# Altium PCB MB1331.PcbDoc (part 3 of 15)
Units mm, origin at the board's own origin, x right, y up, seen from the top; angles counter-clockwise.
Board outline 169.25 x 173.25 mm, 6 copper layers (Top Layer, Signal Layer 1, Signal Layer 2, Signal Layer 3, Signal Layer 4, Bottom Layer), stack 1.556 mm thick; 871 components, 699 nets, 3244 pads, 2370 vias.
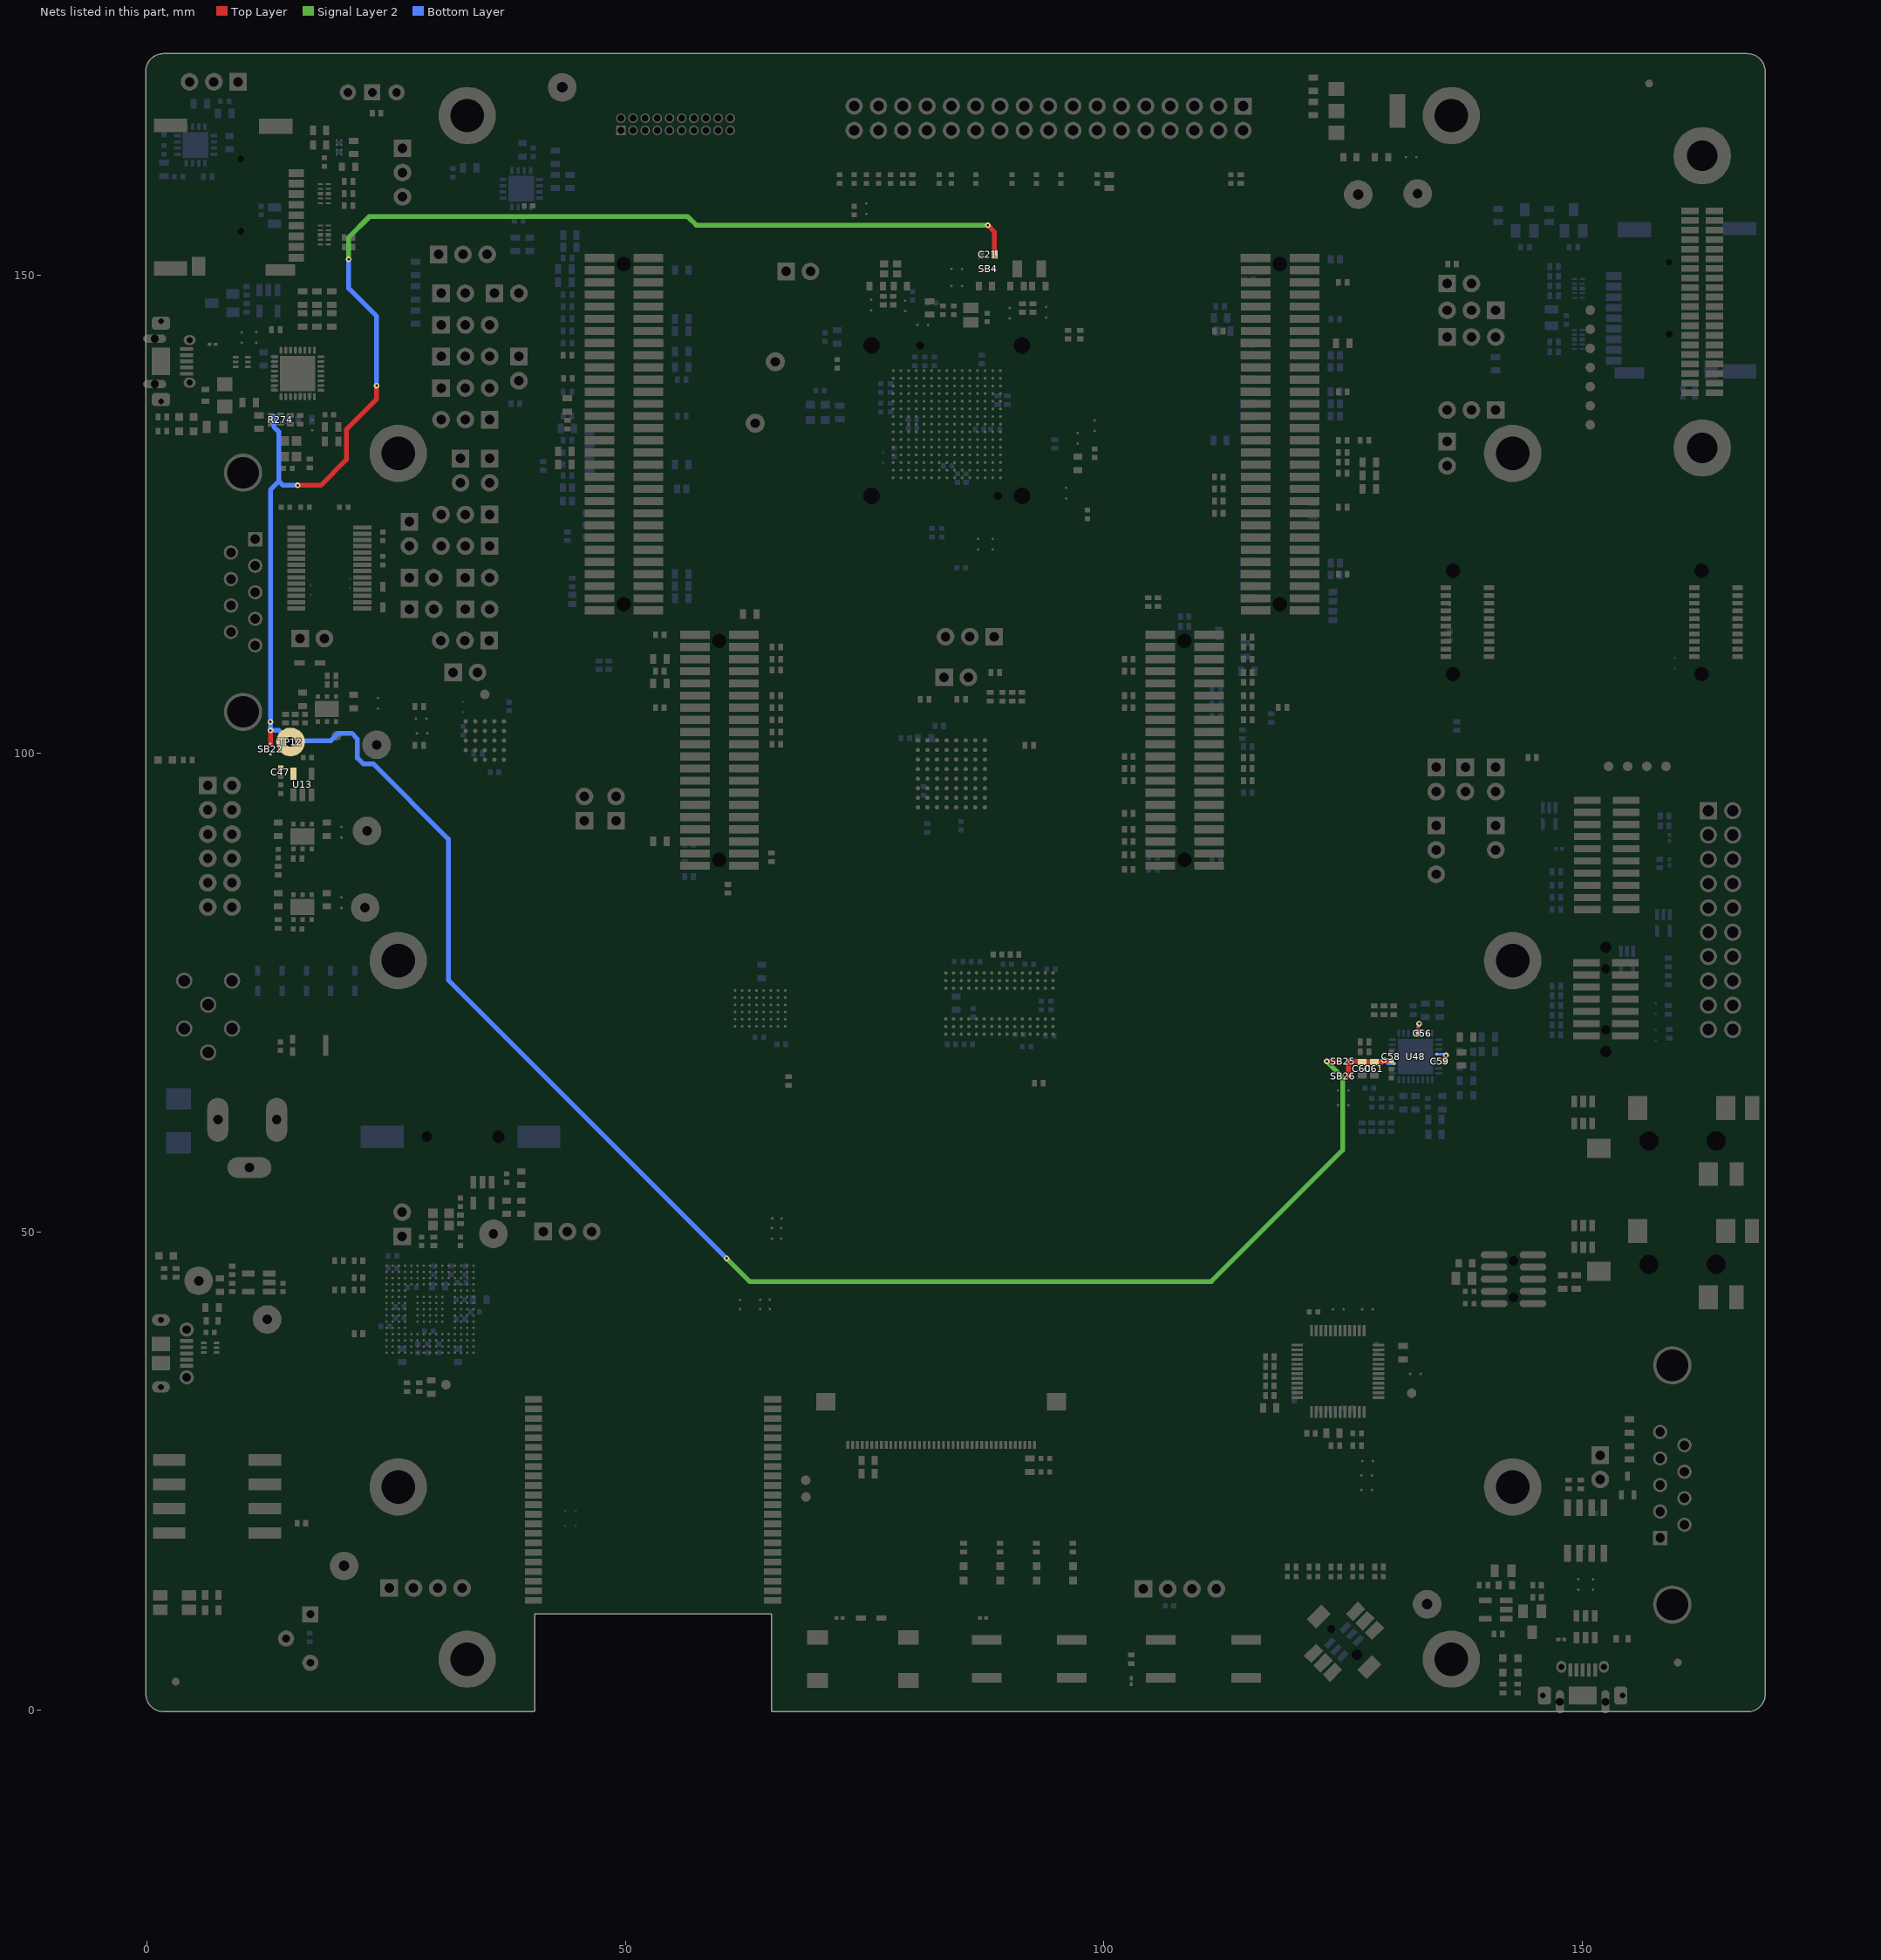
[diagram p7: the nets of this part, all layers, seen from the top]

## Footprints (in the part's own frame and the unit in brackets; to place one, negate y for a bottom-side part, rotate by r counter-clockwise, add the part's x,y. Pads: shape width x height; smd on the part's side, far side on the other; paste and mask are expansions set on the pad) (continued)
ICC_TFBGA225_13X13_STM32H7B3NIH6Q_P080__SOCKET_IRONWOOD_CS1222291MF_REV-A_WITHOUT-3D-SOCKET [mm] "MCD-01577"
  round 0.3 smd mask+0.05: A1(-5.6,5.6) A2(-4.8,5.6) A3(-4,5.6) A4(-3.2,5.6) A5(-2.4,5.6) A6(-1.6,5.6) A7(-0.8,5.6) A8(0,5.6) A9(0.8,5.6) A10(1.6,5.6) A11(2.4,5.6) A12(3.2,5.6) A13(4,5.6) A14(4.8,5.6) A15(5.6,5.6) B1(-5.6,4.8) B2(-4.8,4.8) B3(-4,4.8) B4(-3.2,4.8) B5(-2.4,4.8) B6(-1.6,4.8) B7(-0.8,4.8) B8(0,4.8) B9(0.8,4.8) B10(1.6,4.8) B11(2.4,4.8) B12(3.2,4.8) B13(4,4.8) B14(4.8,4.8) B15(5.6,4.8) C1(-5.6,4) C2(-4.8,4) C3(-4,4) C4(-3.2,4) C5(-2.4,4) C6(-1.6,4) C7(-0.8,4) C8(0,4) C9(0.8,4) C10(1.6,4) C11(2.4,4) C12(3.2,4) C13(4,4) C14(4.8,4) C15(5.6,4) D1(-5.6,3.2) D2(-4.8,3.2) D3(-4,3.2) D4(-3.2,3.2) D5(-2.4,3.2) D6(-1.6,3.2) D7(-0.8,3.2) D8(0,3.2) D9(0.8,3.2) D10(1.6,3.2) D11(2.4,3.2) D12(3.2,3.2) D13(4,3.2) D14(4.8,3.2) D15(5.6,3.2) E1(-5.6,2.4) E2(-4.8,2.4) E3(-4,2.4) E4(-3.2,2.4) E5(-2.4,2.4) E6(-1.6,2.4) E7(-0.8,2.4) E8(0,2.4) E9(0.8,2.4) E10(1.6,2.4) E11(2.4,2.4) E12(3.2,2.4) E13(4,2.4) E14(4.8,2.4) E15(5.6,2.4) F1(-5.6,1.6) F2(-4.8,1.6) F3(-4,1.6) F4(-3.2,1.6) F5(-2.4,1.6) F6(-1.6,1.6) F7(-0.8,1.6) F8(0,1.6) F9(0.8,1.6) F10(1.6,1.6) F11(2.4,1.6) F12(3.2,1.6) F13(4,1.6) F14(4.8,1.6) F15(5.6,1.6) G1(-5.6,0.8) G2(-4.8,0.8) G3(-4,0.8) G4(-3.2,0.8) G5(-2.4,0.8) G6(-1.6,0.8) G7(-0.8,0.8) G8(0,0.8) G9(0.8,0.8) G10(1.6,0.8) G11(2.4,0.8) G12(3.2,0.8) G13(4,0.8) G14(4.8,0.8) G15(5.6,0.8) H1(-5.6,0) H2(-4.8,0) H3(-4,0) H4(-3.2,0) H5(-2.4,0) H6(-1.6,0) H7(-0.8,0) H8(0,0) H9(0.8,0) H10(1.6,0) H11(2.4,0) H12(3.2,0) H13(4,0) H14(4.8,0) H15(5.6,0) J1(-5.6,-0.8) J2(-4.8,-0.8) J3(-4,-0.8) J4(-3.2,-0.8) J5(-2.4,-0.8) J6(-1.6,-0.8) J7(-0.8,-0.8) J8(0,-0.8) J9(0.8,-0.8) J10(1.6,-0.8) J11(2.4,-0.8) J12(3.2,-0.8) J13(4,-0.8) J14(4.8,-0.8) J15(5.6,-0.8) K1(-5.6,-1.6) K2(-4.8,-1.6) K3(-4,-1.6) K4(-3.2,-1.6) K5(-2.4,-1.6) K6(-1.6,-1.6) K7(-0.8,-1.6) K8(0,-1.6) K9(0.8,-1.6) K10(1.6,-1.6) K11(2.4,-1.6) K12(3.2,-1.6) K13(4,-1.6) K14(4.8,-1.6) K15(5.6,-1.6) L1(-5.6,-2.4) L2(-4.8,-2.4) L3(-4,-2.4) L4(-3.2,-2.4) L5(-2.4,-2.4) L6(-1.6,-2.4) L7(-0.8,-2.4) L8(0,-2.4) L9(0.8,-2.4) L10(1.6,-2.4) L11(2.4,-2.4) L12(3.2,-2.4) L13(4,-2.4) L14(4.8,-2.4) L15(5.6,-2.4) M1(-5.6,-3.2) M2(-4.8,-3.2) M3(-4,-3.2) M4(-3.2,-3.2) M5(-2.4,-3.2) M6(-1.6,-3.2) M7(-0.8,-3.2) M8(0,-3.2) M9(0.8,-3.2) M10(1.6,-3.2) M11(2.4,-3.2) M12(3.2,-3.2) M13(4,-3.2) M14(4.8,-3.2) M15(5.6,-3.2) N1(-5.6,-4) N2(-4.8,-4) N3(-4,-4) N4(-3.2,-4) N5(-2.4,-4) N6(-1.6,-4) N7(-0.8,-4) N8(0,-4) N9(0.8,-4) N10(1.6,-4) N11(2.4,-4) N12(3.2,-4) N13(4,-4) N14(4.8,-4) N15(5.6,-4) P1(-5.6,-4.8) P2(-4.8,-4.8) P3(-4,-4.8) P4(-3.2,-4.8) P5(-2.4,-4.8) P6(-1.6,-4.8) P7(-0.8,-4.8) P8(0,-4.8) P9(0.8,-4.8) P10(1.6,-4.8) P11(2.4,-4.8) P12(3.2,-4.8) P13(4,-4.8) P14(4.8,-4.8) P15(5.6,-4.8) R1(-5.6,-5.6) R2(-4.8,-5.6) R3(-4,-5.6) R4(-3.2,-5.6) R5(-2.4,-5.6) R6(-1.6,-5.6) R7(-0.8,-5.6) R8(0,-5.6) R9(0.8,-5.6) R10(1.6,-5.6) R11(2.4,-5.6) R12(3.2,-5.6) R13(4,-5.6) R14(4.8,-5.6) R15(5.6,-5.6)
  round 0 hole 0.85 unplated mask+0.05: NPTH1(7.487,5.322) NPTH2(-8.238,-2.783)
  round 0 hole 1.71 unplated mask+0.05: PTH1(-8.238,7.862) PTH2(7.487,7.862) PTH3(7.487,-7.863) PTH4(-8.238,-7.863)
  Bottom Layer keep-out circle w0.01: c7.487,7.862 r2.5
  Bottom Layer keep-out circle w0.01: c-8.238,7.862 r2.5
  Bottom Layer keep-out circle w0.01: c-8.238,-7.863 r2.5
  Bottom Layer keep-out circle w0.01: c7.487,-7.863 r2.5
  Bottom Layer keep-out region: -0.376,0 -0.376,-2.5 1.224,-2.5 5.024,-6.3 5.076,-6.378 5.094,-6.469 5.094,-6.469 5.094,-6.63 5.028,-6.963 4.839,-7.245 4.557,-7.434 4.224,-7.5 4.224,-7.5 -0.376,-7.5 -0.376,-10.365 9.988,-10.365 9.988,10.365 -0.376,10.365 -0.376,7.5 4.224,7.5 4.557,7.434 4.839,7.245 5.028,6.963 5.094,6.63 5.094,6.63 5.094,6.469 5.076,6.378 5.024,6.3 5.024,6.3 1.224,2.5 -0.376,2.5 -0.376,0 2.124,0 2.124,1.6 5.924,5.4 6.002,5.452 6.093,5.47 6.093,5.47 6.254,5.47 6.587,5.404 6.869,5.215 7.058,4.933 7.124,4.6 7.124,4.6 7.124,-4.6 7.058,-4.933 6.869,-5.215 6.587,-5.404 6.254,-5.47 6.254,-5.47 6.093,-5.47 6.002,-5.452 5.924,-5.4 5.924,-5.4 2.124,-1.6 2.124,0
  Bottom Layer keep-out region: -0.376,0 -0.376,2.5 -1.976,2.5 -5.776,6.3 -5.828,6.378 -5.846,6.469 -5.846,6.469 -5.846,6.63 -5.78,6.963 -5.591,7.245 -5.309,7.434 -4.976,7.5 -4.976,7.5 -0.376,7.5 -0.376,10.365 -10.74,10.365 -10.74,-10.365 -0.376,-10.365 -0.376,-7.5 -4.976,-7.5 -5.309,-7.434 -5.591,-7.245 -5.78,-6.963 -5.846,-6.63 -5.846,-6.63 -5.846,-6.469 -5.828,-6.378 -5.776,-6.3 -5.776,-6.3 -1.976,-2.5 -0.376,-2.5 -0.376,0 -2.876,0 -2.876,-1.6 -6.676,-5.4 -6.754,-5.452 -6.845,-5.47 -6.845,-5.47 -7.006,-5.47 -7.339,-5.404 -7.621,-5.215 -7.81,-4.933 -7.876,-4.6 -7.876,-4.6 -7.876,4.6 -7.81,4.933 -7.621,5.215 -7.339,5.404 -7.006,5.47 -7.006,5.47 -6.845,5.47 -6.754,5.452 -6.676,5.4 -6.676,5.4 -2.876,1.6 -2.876,0
  silkscreen extent -9.65,-9.13 8.75,9.28, body extent -6.55,-6.55 6.55,6.55, height 1.21
ICC_UFBGA201_176+25_10X10_P065 [mm] "IPC"
  round 0.25 smd mask+0.05: A1(-4.55,4.55) A2(-3.9,4.55) A3(-3.25,4.55) A4(-2.6,4.55) A5(-1.95,4.55) A6(-1.3,4.55) A7(-0.65,4.55) A8(0,4.55) A9(0.65,4.55) A10(1.3,4.55) A11(1.95,4.55) A12(2.6,4.55) A13(3.25,4.55) A14(3.9,4.55) A15(4.55,4.55) B1(-4.55,3.9) B2(-3.9,3.9) B3(-3.25,3.9) B4(-2.6,3.9) B5(-1.95,3.9) B6(-1.3,3.9) B7(-0.65,3.9) B8(0,3.9) B9(0.65,3.9) B10(1.3,3.9) B11(1.95,3.9) B12(2.6,3.9) B13(3.25,3.9) B14(3.9,3.9) B15(4.55,3.9) C1(-4.55,3.25) C2(-3.9,3.25) C3(-3.25,3.25) C4(-2.6,3.25) C5(-1.95,3.25) C6(-1.3,3.25) C7(-0.65,3.25) C8(0,3.25) C9(0.65,3.25) C10(1.3,3.25) C11(1.95,3.25) C12(2.6,3.25) C13(3.25,3.25) C14(3.9,3.25) C15(4.55,3.25) D1(-4.55,2.6) D2(-3.9,2.6) D3(-3.25,2.6) D4(-2.6,2.6) D5(-1.95,2.6) D6(-1.3,2.6) D7(-0.65,2.6) D8(0,2.6) D9(0.65,2.6) D10(1.3,2.6) D11(1.95,2.6) D12(2.6,2.6) D13(3.25,2.6) D14(3.9,2.6) D15(4.55,2.6) E1(-4.55,1.95) E2(-3.9,1.95) E3(-3.25,1.95) E4(-2.6,1.95) E12(2.6,1.95) E13(3.25,1.95) E14(3.9,1.95) E15(4.55,1.95) F1(-4.55,1.3) F2(-3.9,1.3) F3(-3.25,1.3) F4(-2.6,1.3) F6(-1.3,1.3) F7(-0.65,1.3) F8(0,1.3) F9(0.65,1.3) F10(1.3,1.3) F12(2.6,1.3) F13(3.25,1.3) F14(3.9,1.3) F15(4.55,1.3) G1(-4.55,0.65) G2(-3.9,0.65) G3(-3.25,0.65) G4(-2.6,0.65) G6(-1.3,0.65) G7(-0.65,0.65) G8(0,0.65) G9(0.65,0.65) G10(1.3,0.65) G12(2.6,0.65) G13(3.25,0.65) G14(3.9,0.65) G15(4.55,0.65) H1(-4.55,0) H2(-3.9,0) H3(-3.25,0) H4(-2.6,0) H6(-1.3,0) H7(-0.65,0) H8(0,0) H9(0.65,0) H10(1.3,0) H12(2.6,0) H13(3.25,0) H14(3.9,0) H15(4.55,0) J1(-4.55,-0.65) J2(-3.9,-0.65) J3(-3.25,-0.65) J4(-2.6,-0.65) J6(-1.3,-0.65) J7(-0.65,-0.65) J8(0,-0.65) J9(0.65,-0.65) J10(1.3,-0.65) J12(2.6,-0.65) J13(3.25,-0.65) J14(3.9,-0.65) J15(4.55,-0.65) K1(-4.55,-1.3) K2(-3.9,-1.3) K3(-3.25,-1.3) K4(-2.6,-1.3) K6(-1.3,-1.3) K7(-0.65,-1.3) K8(0,-1.3) K9(0.65,-1.3) K10(1.3,-1.3) K12(2.6,-1.3) K13(3.25,-1.3) K14(3.9,-1.3) K15(4.55,-1.3) L1(-4.55,-1.95) L2(-3.9,-1.95) L3(-3.25,-1.95) L4(-2.6,-1.95) L12(2.6,-1.95) L13(3.25,-1.95) L14(3.9,-1.95) L15(4.55,-1.95) M1(-4.55,-2.6) M2(-3.9,-2.6) M3(-3.25,-2.6) M4(-2.6,-2.6) M5(-1.95,-2.6) M6(-1.3,-2.6) M7(-0.65,-2.6) M8(0,-2.6) M9(0.65,-2.6) M10(1.3,-2.6) M11(1.95,-2.6) M12(2.6,-2.6) M13(3.25,-2.6) M14(3.9,-2.6) M15(4.55,-2.6) N1(-4.55,-3.25) N2(-3.9,-3.25) N3(-3.25,-3.25) N4(-2.6,-3.25) N5(-1.95,-3.25) N6(-1.3,-3.25) N7(-0.65,-3.25) N8(0,-3.25) N9(0.65,-3.25) N10(1.3,-3.25) N11(1.95,-3.25) N12(2.6,-3.25) N13(3.25,-3.25) N14(3.9,-3.25) N15(4.55,-3.25) P1(-4.55,-3.9) P2(-3.9,-3.9) P3(-3.25,-3.9) P4(-2.6,-3.9) P5(-1.95,-3.9) P6(-1.3,-3.9) P7(-0.65,-3.9) P8(0,-3.9) P9(0.65,-3.9) P10(1.3,-3.9) P11(1.95,-3.9) P12(2.6,-3.9) P13(3.25,-3.9) P14(3.9,-3.9) P15(4.55,-3.9) R1(-4.55,-4.55) R2(-3.9,-4.55) R3(-3.25,-4.55) R4(-2.6,-4.55) R5(-1.95,-4.55) R6(-1.3,-4.55) R7(-0.65,-4.55) R8(0,-4.55) R9(0.65,-4.55) R10(1.3,-4.55) R11(1.95,-4.55) R12(2.6,-4.55) R13(3.25,-4.55) R14(3.9,-4.55) R15(4.55,-4.55)
  silkscreen extent -5.22,-5.07 5.07,5.23, body extent -5.07,-5.07 5.07,5.07, height 0.61
IND_0402_MURATA_BLM15H_H0P5 [mm] "MCD-01610"
  rect 0.65x0.9 smd mask+0.05: 1(-0.475,0) 2(0.475,0)
  silkscreen extent -0.05,-0.28 0.05,0.28, body extent -0.53,-0.28 0.53,0.28, height 0.55
IND_0603_H0P8 [mm]
  rect 0.7x0.9 smd mask+0.05: 1(-0.7,0) 2(0.7,0)
  silkscreen extent -0.2,-0.4 0.2,0.4, body extent -0.8,-0.4 0.8,0.4, height 0.8
L0603 [mm]
  rect 0.8x0.95 smd mask+0.05: 1(-0.8,0) 2(0.8,0)
  silkscreen extent -1.33,-0.6 1.33,0.6, body extent -0.87,-0.47 0.87,0.47, height 0.95
L0805_H0P9 [mm]
  rect 1.1x1.6 smd mask+0.05: 1(-0.75,0) 2(0.75,0)
  silkscreen extent -0.08,-0.7 0.08,0.7, body extent -1.07,-0.7 1.07,0.7, height 1.2
LED_0603_OSRAM_LG-Q396-PS-35_GREEN_1A2K_H0P4 [mm]
  rect 0.8x0.8 smd mask+0.05: 1(-0.75,0) 2(0.75,0)
  silkscreen extent -0.85,-0.53 1.28,0.53, body extent -0.85,-0.45 0.85,0.45, height 0.6
LED_0603_OSRAM_LO-Q976-PS-25_ORANGE_1A2K_H0P8 [mm]
  rect 0.8x0.8 smd mask+0.05: 1(-0.75,0) 2(0.75,0)
  silkscreen extent -0.85,-0.53 1.28,0.53, body extent -0.85,-0.45 0.85,0.45, height 0.8
LED_0603_OSRAM_LY-Q396-P1Q2-36_YELLOW_1A2K_H0P4 [mm]
  rect 0.8x0.8 smd mask+0.05: 1(-0.75,0) 2(0.75,0)
  silkscreen extent -0.85,-0.53 1.28,0.53, body extent -0.85,-0.45 0.85,0.45, height 0.4
LED_0603_VISHAY_VLMS1300-GS08_RED_1A2K_H0P8 [mm]
  rect 0.8x0.8 smd mask+0.05: 1(-0.75,0) 2(0.75,0)
  silkscreen extent -0.85,-0.53 1.28,0.53, body extent -0.85,-0.45 0.85,0.45, height 0.8
LED_BI-GR_HSMF-A201-A00J1 [mm] "MCD-00051"
  rect 1.1x1.5 smd mask+0.05: 1(-0.75,-1.5) 2(-0.75,1.5) 3(0.75,1.5) 4(0.75,-1.5)
  silkscreen extent -1.65,-1.85 1.5,1.7, body extent -1.5,-1.85 1.5,1.85, height 2.1
MIRE_PLACE_SMD_0P8MM [mm]
  round 0.8 smd paste-10 mask+0.2: 1(0,0)
  Top Layer keep-out circle w0.01: c0,0 r0.804
MOD_WIFI_INVENTEK_ISM43362 [mm]
  rect 1.8x0.7 smd mask+0.1: 1(12.5,-12.3) 2(12.5,-11.3) 3(12.5,-10.3) 4(12.5,-9.3) 5(12.5,-8.3) 6(12.5,-7.3) 7(12.5,-6.3) 8(12.5,-5.3) 9(12.5,-4.3) 10(12.5,-3.3) 11(12.5,-2.3) 12(12.5,-1.3) 13(12.5,-0.3) 14(12.5,0.7) 15(12.5,1.7) 16(12.5,2.7) 17(12.5,3.7) 18(12.5,4.7) 19(12.5,5.7) 20(12.5,6.7) 21(12.5,7.7) 22(12.5,8.7) 23(-12.5,8.7) 24(-12.5,7.7) 25(-12.5,6.7) 26(-12.5,5.7) 27(-12.5,4.7) 28(-12.5,3.7) 29(-12.5,2.7) 30(-12.5,1.7) 31(-12.5,0.7) 32(-12.5,-0.3) 33(-12.5,-1.3) 34(-12.5,-2.3) 35(-12.5,-3.3) 36(-12.5,-4.3) 37(-12.5,-5.3) 38(-12.5,-6.3) 39(-12.5,-7.3) 40(-12.5,-8.3) 41(-12.5,-9.3) 42(-12.5,-10.3) 43(-12.5,-11.3) 44(-12.5,-12.3)
  Keep-Out Layer region: -12.5,20 12.5,20 12.5,10 -12.5,10
  silkscreen extent -12.7,-20.2 13.4,20.2, body extent -12.5,-20 12.5,20.19, height 4.1
MOS_SOT23 [mm]
  rect 1x1.4 smd mask+0.05: 1(-0.95,-1.1) 2(0.95,-1.1) 3(0,1.1)
  silkscreen extent -1.63,-0.82 1.63,0.82, body extent -1.56,-1.25 1.56,1.25, height 1.1
MOS_SOT23-5L [mm]
  rect 0.6x1.3 smd mask+0.05: 1(-0.95,-1.1) 2(0,-1.1) 3(0.95,-1.1) 4(0.95,1.1) 5(-0.95,1.1)
  silkscreen extent -1.6,-0.95 1.6,0.97, body extent -1.52,-1.25 1.52,1.25, height 1.45
NPN_SOT23 [mm]
  rect 1x1.4 smd mask+0.05: 1(-0.95,-1.1) 2(0.95,-1.1) 3(0,1.1)
  silkscreen extent -1.63,-0.82 1.63,0.82, body extent -1.56,-1.25 1.56,1.25, height 1.1
OSC_NDK_NZ2520SB_4P [mm]
  rect 1x1 smd mask+0.05: 1(-0.825,-0.625) 2(0.825,-0.625) 3(0.825,0.625) 4(-0.825,0.625)
  silkscreen extent -1.43,-1.22 1.2,1.05, body extent -1.3,-1.05 1.3,1.05, height 0.91
POT_BOURNS_3386P [mm]
  rect 1.7x1.7 hole 0.8 mask+0.05: 1(-2.54,0.02)
  round 1.7 hole 0.8 mask+0.05: 2(0,-2.52) 3(2.54,0.02)
  silkscreen extent -4.8,-4.8 4.8,4.8, body extent -4.8,-4.8 4.8,4.81, height 4.96
PTH_M1261-3005-N_3P5X6_M3_H14 [mm]
  round 6 hole 3.5 mask+0.05: 1(0,0)
  silkscreen extent -3.25,-3.25 3.25,3.25, body extent -2.5,-2.5 2.5,2.5, height 14
R0402 [mm]
  rect 0.51x0.7 smd mask+0.05: 1(-0.45,0) 2(0.45,0)
  silkscreen extent 0,-0.3 0,0.3, body extent -0.52,-0.3 0.52,0.3, height 0.4
R0603 [mm]
  rect 0.64x1 smd mask+0.05: 1(-0.7,0) 2(0.7,0)
  silkscreen extent -1.05,-0.58 1.05,0.58, body extent -0.9,-0.5 0.9,0.5, height 0.56
R0603_H0P45 [mm]
  rect 0.64x1 smd mask+0.05: 1(-0.7,0) 2(0.7,0)
  silkscreen extent -1.05,-0.58 1.05,0.58, body extent -0.9,-0.5 0.9,0.5, height 0.56
R0805 [mm]
  rect 0.85x1.3 smd mask+0.05: 1(-0.875,0) 2(0.875,0)
  silkscreen extent -0.33,-0.67 0.33,0.67, body extent -1.05,-0.68 1.05,0.68, height 0.65
REG_SOT23-5L [mm]
  rect 0.6x1.3 smd mask+0.05: 1(-0.95,-1.1) 2(0,-1.1) 3(0.95,-1.1) 4(0.95,1.1) 5(-0.95,1.1)
  silkscreen extent -1.6,-0.95 1.6,0.97, body extent -1.52,-1.25 1.52,1.25, height 1.1
REG_SOT223-TAB [mm]
  rect 1.5x1.65 smd mask+0.05: 1(-2.3,-3.175) 2(0,-3.175) 3(2.3,-3.175)
  rect 3.5x1.65 smd mask+0.05: 4(0,3.175)
  silkscreen extent -3.35,-2.15 3.35,2.12, body extent -3.35,-3.48 3.35,3.48, height 1.8
Sheetbox_6L2S [mil] "Sheetbox 6 layers / 2 silkscreens"
  round 20 on Mech16: 1(813.5,208.05) 1(2736.63,208.05)
SOLDER-BRIDGE_R0402-0R [mil] "MCD-01619"
  round 10 smd paste-393.7: 1(-17.72,0) 2(20.67,0)
  Top Layer region: 1.48,13.78 8.37,0 1.48,-13.78 30.51,-13.78 30.51,13.78
  Top Layer region: -30.51,-13.78 -30.51,13.78 -8.37,13.78 -1.48,0 -8.37,-13.78
  silkscreen extent -33,-17 33,17, body extent -20,-12 20,12, height 14
SOLDER-BRIDGE_R0603-0R [mil]
  round 10 smd paste-393.7: 1(-19.68,0) 2(23.62,0)
  Top Layer region: -47.24,-19.68 -47.24,19.68 -15.75,19.68 3.94,0 -15.75,-19.68 -47.24,-19.68
  Top Layer region: -5.91,19.68 13.78,0 -5.91,-19.68 47.24,-19.68 47.24,19.68 -5.91,19.68
  silkscreen extent -50,-23 50,23, body extent -36,-20 36,20, height 22
STICKER_25X9 [mm] "Sticker 25mm x 9mm"
  silkscreen extent -12.5,-4.5 12.5,4.5
SWI_C&K_KSC721GLFS_BLUE [mm] "BLUE"
  rect 3.1x1 smd mask+0.05: 1(-4.45,2) 2(4.45,2) 3(-4.45,-2) 4(4.45,-2)
  silkscreen extent -3.25,-3.25 3.25,3.25, body extent -5,-3.25 5,3.25, height 4.3
SWI_EAO_09-03290-01_EXTENDED_STRAIGHT_BLACK [mm]
  rect 1.7x1.7 hole 0.9 mask+0.05: 1(0,0)
  round 1.7 hole 0.9 mask+0.05: 2(0,-2.54) 3(0,2.54)
  silkscreen extent -1.25,-5 1.25,5, body extent -1.25,-5 1.25,5, height 7.9
SWI_WEALTHMETAL_TD-0341_4P_BLACK [mm]
  rect 1.52x2.16 smd mask+0.05: 1(-2.25,-4.75) 2(-2.25,4.75) 3(2.25,-4.75) 4(2.25,4.75)
  silkscreen extent -3,-3.5 3,3.5, body extent -3,-5.15 3,5.15, height 7.55
SWI_XIEJIA_MT-008A_6P [mm] "MCD-00132"
  rect 1.8x1.1 smd mask+0.05: 1(-3.1,1.4) 2(-3.1,0) 3(-3.1,-1.4) 4(3.1,1.4) 5(3.1,0) 6(3.1,-1.4)
  rect 2.2x1.4 smd mask+0.05: 7(0,3.75) 8(0,-3.75)
  round 0 hole 0.8 unplated paste-10 mask+0.05: NPTH1(0,1.9)
  round 0 hole 1.1 unplated paste-10 mask+0.05: NPTH2(0,-1.9)
  silkscreen extent -3.7,-3.7 3.7,3.7, body extent -3.85,-3.75 3.85,3.75, height 5.2
TP_PTH-1MM_TEST-TERMINAL_RS_262-2185_RED [mm] "MCD-00712"
  round 3 hole 1 mask+0.05: 1(0,0)
  silkscreen extent -1.63,-1.62 1.63,1.62, body extent -1.24,-1.25 1.25,1.25, height 4.85
TP_PTH-1P02MM_TEST-TERMINAL_RS_101-2391_BLACK [mm] "MCD-00713"
  round 3 hole 1.1 mask+0.05: 1(0,0)
  silkscreen extent -1.63,-1.62 1.63,1.62, body extent -1.24,-1.25 1.25,1.25, height 4.85
TP_PTH_1MM_2MM [mm] "MCD-01506"
  round 2 hole 1 mask+0.05: 1(0,0)
  silkscreen extent -1.2,-1.2 1.2,1.2
TP_SMD_1MM [mm]
  round 1 smd paste-10 mask+0.05: 1(0,0)
  silkscreen extent -0.7,-0.7 0.7,0.7

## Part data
B1: library part MCD-00001, "Non-Open Push-Button 0.1A 24V BLACK", Manufacturer=WEALTHMETAL, Manufacturer_Part_Number=TD-0341
B2 B3: library part MCD-00176, "Switch HW BLUE High4.3mm 2.25 Newtons", Manufacturer=C&K, Manufacturer_Part_Number=KSC721GLFS
B4: library part MCD-00132, "Joystick, 4 dir, 1 OK", Manufacturer="XIEJIA Electronics", Manufacturer_Part_Number=MT-008A
C1 C2: library part MCD-00243, "Capacitor, MLCC, 10uF, 6V3, X5R, 10%, 0603, T=0,8mm", Manufacturer=YAGEO, Manufacturer_Part_Number=CC0603KRX5R5BB106, Package=C0603
C3 C5 C6 C7 C8 C9 C11 C12 C13 C14 C15 C16 C17 C30 C32 C34 C35 C36 C37 C38 C39 C40 C41 C43 C45 C51 C54 C55 C56 C57 C58 C59 C62 C64 C68 C69 C71 C73 C76 C78 C79 C87 C91 C95 C97 C98 C99 C101 C104 C107 C108 C110 C111 C112 C113 C114 C115 C116 C117 C119 C120 C121 C122 C123 C124 C125 C126 C127 C128 C129 C130 C131 C132 C134 C135 C136 C137 C138 C139 C140 C141 C143 C145 C146 C149 C150 C152 C153 C154 C155 C156 C158 C167 C171 C172 C173 C174 C175 C176 C178 C180 C181 C182 C183 C184 C185 C186 C189 C190 C191 C192 C193 C194 C195 C196 C197 C198 C199: library part MCD-00006, "Capacitor, MLCC, 100nF, 16V, X7R, 10%, 0402, T=0.5mm", Alternate_Manufacturer=MURATA, Alternate_Manufacturer_Part_Number=GCM155R71C104KA55D, Manufacturer=YAGEO, Manufacturer_Part_Number=CC0402KRX7R7BB104, Package=C0402
C4 C33 C60 C61 C67 C70 C88 C89 C147 C148 C160 C161 C164 C179: library part MCD-00010, "Capacitor, MLCC, 1uF, 16V, X5R, 10%, 0603, T=0,8mm", Manufacturer=YAGEO, Manufacturer_Part_Number=CC0603KRX5R7BB105, Package=C0603
C10 C18: library part MCD-00198, "Capacitor, MLCC, 1nF, 16V, X7R, 10%, 0402, T=0.5mm", Manufacturer=YAGEO, Manufacturer_Part_Number=CC0402KRX7R7BB102, Package=C0402
C19 C47 C48 C90 C92 C93 C109 C118 C169 C170: library part MCD-00095, "Capacitor, MLCC, 1uF, 6V3, X5R, 10%, 0402, T=0,5mm", Alternate_Manufacturer=MURATA, Alternate_Manufacturer_Part_Number=GRM155R60J105KE19, Manufacturer_Part_Number=GRM155R61E105KA12, Package=C0402
C20 C46 C65 C80 C81 C82 C83 C84: library part MCD-00011, "Capacitor, MLCC, 10nF, 16V, X7R, 10%, 0402, T=0.5mm", Manufacturer=YAGEO, Manufacturer_Part_Number=CC0402KRX7R7BB103, Package=C0402
C21 C42 C44 C50 C53 C102 C133 C142 C144: library part MCD-01121, "Capacitor, MLCC, 4.7uF, 10V, X5R, 20%, 0603, T=0,8mm", Manufacturer=MURATA, Manufacturer_Part_Number=GRM188R61A475ME15, Package=C0603
C22 C23 C25 C26: library part MCD-01726, "Capacitor, MLCC, 2.7pF, 50V, NPO, -+0.25pF 0603", Manufacturer=YAGEO, Manufacturer_Part_Number=CC0603CRNPO9BN2R7, Package=C0603
C24: library part MCD-01341, "Capacitor, MLCC, 10uF, 6V3, X5R, 20%, 0603, T=0,8mm", Manufacturer=MURATA, Manufacturer_Part_Number=GRM188R60J106ME47D, Package=C0603
C27 C28: library part MCD-01716, "Capacitor, MLCC, 10uF, 6V3, X5R, 20%, 0402, T=0.5mm", Manufacturer=YAGEO, Manufacturer_Part_Number=CC0402MRX5R5BB106, Package=C0402
C29 C74: library part MCD-00205, "Capacitor, MLCC, 100pF, 50V, NPO, 5%, 0402, T=0,5mm", Manufacturer=YAGEO, Manufacturer_Part_Number=CC0402JRNPO9BN101, Package=C0402
C31: library part MCD-00007, "Capacitor, Tantalum, 4.7uF, 16V, 10%, 4ohms, pkg Type_A (3216 metric), T=1.6mm", Manufacturer=AVX, Manufacturer_Part_Number=TAJA475K016R, Package=Type_A
C49 C52: library part MCD-00097, "Capacitor, MLCC, 4.7uF, 16V, X5R, 20%, 0603, T=0,8mm", Alternate_Manufacturer=Murata, Alternate_Manufacturer_Part_Number=GRM188R61C475MAAJ, Manufacturer=MURATA, Manufacturer_Part_Number=GRM188R61C475KE11, Package=C0603
C63: library part MCD-00238, "Capacitor, MLCC, 1uF, 6V3, X5R, 10%, 0603, T=0,8mm", Manufacturer=YAGEO, Manufacturer_Part_Number=CC0603KRX5R5BB105, Package=C0603
C66: library part MCD-00211, "Capacitor, MLCC, 100nF, 16V, X7R, 10%, 0603, T=0,8mm", Manufacturer=YAGEO, Manufacturer_Part_Number=CC0603KRX7R7BB104, Package=C0603
C72 C85 C177: library part MCD-00009, "Capacitor, MLCC, 4.7uF, 16V, X5R, 10%, 0603, T=0.8mm", Manufacturer=YAGEO, Manufacturer_Part_Number=CC0603KRX5R7BB475, Package=C0603
C75: library part MCD-00014, "Capacitor, MLCC, 10uF, 25V, X5R, 10%, 0805, T=0,85mm", Manufacturer=YAGEO, Manufacturer_Part_Number=CC0805KRX5R8BB106, Package=C0805
C77 C105 C187 C188: library part MCD-00012, "Capacitor, MLCC, 2.2uF, 10V, X5R, 10%, 0603, T=0,8mm", Alternate_Manufacturer=KEMET, Alternate_Manufacturer_Part_Number=C0603C225K8PACTU, Manufacturer=YAGEO, Manufacturer_Part_Number=CC0603KRX5R6BB225, Package=C0603
C86: library part MCD-01356, "Capacitor, MLCC, 4.7uF, 6V3, X5R, 20%, 0402, T=0,5mm", Manufacturer=MURATA, Manufacturer_Part_Number=GRM155R60J475ME47, Package=C0402
C94 C100: library part MCD-01974, "Capacitor, MLCC, 4.7uF, 16V, 0805, X5R, 10%, T=1,25mm", Alternate_Manufacturer=KEMET, Alternate_Manufacturer_Part_Number=C0805C475K4PACTU, Manufacturer="TAIYO YUDEN", Manufacturer_Part_Number=EMK212ABJ475KG-T, Package=C0805
C96: library part MCD-00237, "Capacitor, MLCC, 100nF, 6V3, X5R, 10%, 0603, T=0,8mm", Manufacturer=YAGEO, Manufacturer_Part_Number=CC0603KRX5R5BB104, Package=C0603
C103 C106: library part MCD-00716, "Capacitor, MLCC, 3.6nF, 50V, C0G, 5%, 0603, T=0,8mm", Alternate_Manufacturer=MURATA, Alternate_Manufacturer_Part_Number=GRM1885C1H362JA01D, Manufacturer=KEMET, Manufacturer_Part_Number=C0603C362J5GACTU, Package=C0603
C151 C159: library part MCD-00555, "Capacitor, MLCC, 22nF, 10%, 25V, X7R, 0603, T=0,8mm", Manufacturer=YAGEO, Manufacturer_Part_Number=CC0603KRX7R8BB223, Package=C0603
C157: library part MCD-00142, "Capacitor, Tantalum, 220uF, 10V, 10%, 500mOhms, pkg Type_C (6032 metric), T=2.6mm", Manufacturer=AVX, Manufacturer_Part_Number=TAJC227K010R, Package=Type_C
C162 C168: library part MCD-00694, "Capacitor, MLCC, 1.8nF, 50V, X7R, 10%, 0402, T=0.5mm", Manufacturer=YAGEO, Manufacturer_Part_Number=CC0402KRX7R9BB182, Package=C0402
C163: library part MCD-00099, "Capacitor, MLCC, 10uF, 10V, X5R, 10%, 0603, T=0,8mm", Manufacturer=MURATA, Manufacturer_Part_Number=GRM188R61A106KE69D, Package=C0603
C165 C166: library part MCD-00304, "Capacitor, MLCC, 150pF, 50V, COG, 5%, 0603, T=0,8mm", Manufacturer=YAGEO, Manufacturer_Part_Number=CC0603JRNPO9BN151, Package=C0603
C200 C201: library part MCD-00015, "Capacitor, MLCC, 10pF, 50V, NPO, 5%, 0402, T=0,5mm", Manufacturer=YAGEO, Manufacturer_Part_Number=CC0402JRNPO9BN100, Package=C0402
CN1: library part MCD-00583, "Header, 17x2, 2.54mm, VR, TH, Height 8.89mm/2.92mm, shrouded", Alternate_Manufacturer=WINPIN, Alternate_Manufacturer_Part_Number=BHFS03-34G01BT1, Manufacturer=SAMTEC, Manufacturer_Part_Number=TST-117-01-T-D
CN2: library part MCD-00138, "Socket, 20x2, 1.0mm, VR, SMT, Height 2.26mm. Symbol & Footprint dedicated to MB1183 & MB1379 camera modules (not in line with Samtec datasheet)", Manufacturer=SAMTEC, Manufacturer_Part_Number=CLM-120-02-L-D
CN3 CN28: library part MCD-00023, "MicroSD Card Conn, Reversed-Type, Mnt Push-Push, Positionning holes", Manufacturer=YAMAICHI, Manufacturer_Part_Number=PJS008-2003-1
CN4: library part MCD-00147, "Socket for MB1299, 10x2, 1.27mm, VR, TH, Height 4.30mm/2.40mm", Alternate_Manufacturer=JIUBABA, Alternate_Manufacturer_Part_Number=234220S1410, Manufacturer=FCI, Manufacturer_Part_Number=20021311-00020T4LF
CN5 CN6: library part MCD-00576, "Header 30x2, 1.27mm, VR, CMS, Height 7.24mm", Alternate_Manufacturer=JIUBABA, Alternate_Manufacturer_Part_Number=P1039-2*30MGF-089-1A, Manufacturer=SAMTEC, Manufacturer_Part_Number=FTR-130-53-L-D-LC
CN7 JP5 JP10 JP13 JP14 JP16 JP22 JP24 JP25 JP26 JP27 JP28 JP30 JP31 JP34 JP38 JP39 JP40: library part MCD-00045, "Header, 2x1, 2,54mm, VR, TH, Height 5.84mm/2.54mm", Alternate_Manufacturer="JIUBABA; LIANYI", Alternate_Manufacturer_Part_Number=313102S111116;313102S111116, Manufacturer=SAMTEC, Manufacturer_Part_Number=TSW-102-07-x-S
CN8 CN27: library part MCD-00661, "USB-MICRO-AB Receptacle, RA, SMT + DIP, Standard, Top Mount, USB certified (symbol & footprint compatible with MCD-00022)", Manufacturer=HIROSE, Manufacturer_Part_Number=ZX62RD-AB-5P8(30)
CN9 CN22: library part MCD-01978, "DB9_Male, RA, TH, height 13.575mm/3.8mm", Manufacturer=TYCO, Manufacturer_Part_Number=2301843-2, Package=TH
CN10 CN11: library part MCD-00675, "Socket High Speed, 10x2, 0.8mm, Center Strip Contacts, VR, SMT, Height 5.33 mm", Manufacturer=SAMTEC, Manufacturer_Part_Number=ERF8-010-05.0-S-DV-TR, Package=ERF8
CN12 CN13: library part MCD-00578, "Header 20x2, 1.27mm, VR, CMS, Height 7.24mm", Alternate_Manufacturer=JIUBABA, Alternate_Manufacturer_Part_Number=P1039-2*20MGF-089-1A, Manufacturer=SAMTEC, Manufacturer_Part_Number=FTR-120-53-L-D-LC
CN14: library part MCD-01058, "Header, 2.54mm, 10x2, VR, TH, Height 9.1mm/3,1mm", Alternate_Manufacturer=CVILUX, Alternate_Manufacturer_Part_Number=CH87-20-2-V-1-00, Manufacturer=SAMTEC, Manufacturer_Part_Number=TST-110-01-G-D
CN15: library part MCD-00557, "Header 10x2, 1.27mm, VR, CMS, Height 3.05mm", Alternate_Manufacturer=JIUBABA, Alternate_Manufacturer_Part_Number=P127B-2*10MGF-079-1E7A, Manufacturer=SAMTEC, Manufacturer_Part_Number=FTSH-110-01-L-DV-007-K
CN16: library part MCD-01226, "Header 5x2, 1.27mm, Dual row, Straight, Surface mount, vertical male connector. 3.05mm lead. Mates with FFSD connector. Footprint compatible with FTSH-107-01-L-DV,-K,-A,-P,-ES (STDC14 MEDIUM)", Alternate_Manufacturer=JIUBABA, Alternate_Manufacturer_Part_Number=P127B-2x05MGF-079-1A, Manufacturer=SAMTEC, Manufacturer_Part_Number=FTSH-105-01-L-DV-007-K
CN17: library part MCD-00173, "DC-Power-Jack, 2.5mm, 5A, RA, TH", Manufacturer=CLIFF, Manufacturer_Part_Number=DC10B
CN18 CN20: library part MCD-00263, "Connector Jack Socket Stereo 3.5mm, 4 pins, RA, SMT, Black", Manufacturer=QIAOD, Manufacturer_Part_Number=PJ3028B-3_4P
CN19: library part MCD-00032, "Header, 2x1, 2,54mm, VR, TH, Height 5.84mm/2.54mm", Alternate_Manufacturer=JIUBABA, Alternate_Manufacturer_Part_Number=313102S111116, Manufacturer=SAMTEC, Manufacturer_Part_Number=TSW-102-07-x-S
CN21: library part MCD-00028, "USB-MICRO-B, 0.65mm, RA, SMT, Bottom Mount,", Manufacturer=MOLEX, Manufacturer_Part_Number=1050170001
CN23: library part MCD-01992, "FFC et FPC connector 0.5MM 40P LNG MTL FITNG SMT VERT MNT", Manufacturer=HIROSE, Manufacturer_Part_Number=FH52E-40S-05SH
CN24: library part MCD-00131, "Socket, 4x2, 2.54mm, RA, SMT, Height 5.72mm", Alternate_Manufacturer=JIUBABA, Alternate_Manufacturer_Part_Number=F206A-2x04MGF-LA, Manufacturer=SAMTEC, Manufacturer_Part_Number=SSM-104-L-DH
CN25 CN26: library part MCD-00029, "Header, 4x1, 2,54mm, VR, TH, Height 5.84mm/2.54mm", Manufacturer=SAMTEC, Manufacturer_Part_Number=TSW-104-07-x-S
CN29: library part MCD-00558, "Battery Coin Cell holder, CR1220_12mm, Height 4.25mm", Manufacturer=HARWIN, Manufacturer_Part_Number=S8411-45R
CN30: library part MCD-00610, "Surface mount, vertical male connector. Double row of 5 pins, 1.27mm pitch, 3.05mm lead. Mates with FFSD connector", Alternate_Manufacturer=JIUBABA, Alternate_Manufacturer_Part_Number=P127B-2x05MGF-079-1A, Manufacturer=SAMTEC, Manufacturer_Part_Number=FTSH-105-01-L-DV-K
D1 D2 D3 D4 D5 D6 D7 D8: library part MCD-00034, Manufacturer=STMICROELECTRONICS
H1 H2 H3 H4 H5 H6 H7 H8 H9 H10: library part MCD-00035, "POSITION HOLE C6D3R5", Manufacturer=n/a
HW21: library part MCD-00547, "Sticker to mention board CPN code", Manufacturer=n/a
HW23: library part MCD-00235, "Sticker to mention board reference + serial number", Manufacturer=n/a
JP1 JP4 JP6 JP7 JP8 JP9 JP11 JP12 JP17 JP19 JP23 JP32 JP37: library part MCD-00684, "Header, 3x1, 2,54mm, VR, TH, Height 5.84mm/2.54mm - Shunt Fitted 1-2 by default", Manufacturer=SAMTEC, Manufacturer_Part_Number=TSW-103-07-F-S
JP2 JPME1: library part MCD-00111, "Header, 3x1, 2,54mm, VR, TH, Height 5.84mm/2.54mm", Manufacturer=SAMTEC, Manufacturer_Part_Number=TSW-103-07-F-S
JP3 JP15 JP18 JP20 JP21: library part MCD-00683, "Header, 2x1, 2,54mm, VR, TH, Height 5.84mm/2.54mm - Shunt Fitted by default", Alternate_Manufacturer=LIANYI, Alternate_Manufacturer_Part_Number=313102S111116, Manufacturer=SAMTEC, Manufacturer_Part_Number=TSW-102-07-x-S
JP29: library part MCD-01147, "Header, 6x2, 2,54mm, VR, TH, Height 5.84mm/2.54mm - Shunt Fitted 1-2", Manufacturer=SAMTEC, Manufacturer_Part_Number=TSW-106-07-x-D
JP35: library part MCD-00685, "Header, 3x1, 2,54mm, VR, TH, Height 5.84mm/2.54mm - Shunt Fitted 2-3 by default", Manufacturer=SAMTEC, Manufacturer_Part_Number=TSW-103-07-F-S
L1: library part MCD-01340, "Inductor, 2.2uH, 20%, Isat 1.2A, DCR 0.228Ohm, 0805", Manufacturer=MURATA, Manufacturer_Part_Number=DFE201210U-2R2M{}P2, Package=L0805
L2: library part MCD-00150, "Through HOLE DC power EMI line filter, 40dB min (1MHz - 1GHz) insertion loss", Manufacturer=MURATA
LD1 LD6 LD7 LD11: library part MCD-00588, "LED Green, 0603 SMD, Forward Voltage Typ=2V, Max=2.5V", Alternate_Manufacturer="VISHAY SEMICONDUCTOR OPTO DIVISION", Alternate_Manufacturer_Part_Number=VLMTG1300-GS08, Manufacturer="OSRAM OPTO SEMICONDUCTORS", Manufacturer_Part_Number="LG Q396-PS-35", Package="LED 0603"
LD2 LD5 LD8 LD10: library part MCD-00587, "LED Red, 0603 SMD, 2V Forward Voltage", Alternate_Manufacturer="OSRAM OPTO SEMICONDUCTORS", Alternate_Manufacturer_Part_Number="LS Q976-NR-1", Manufacturer=VISHAY, Manufacturer_Part_Number=VLMS1300-GS08, Package="LED 0603"
LD3: library part MCD-01061, "LED Yellow, 0603 SMD, Forward Voltage min=1.7V, Typ=2V, Max=2.3V", Manufacturer="OSRAM OPTO SEMICONDUCTORS", Manufacturer_Part_Number="LY Q396-P1Q2-36"
LD4: library part MCD-00590, "LED Orange, 0603 SMD, Forward Voltage Min=1.6V, Max=2.4V", Alternate_Manufacturer="VISHAY SEMICONDUCTOR OPTO DIVISION", Alternate_Manufacturer_Part_Number=VLMO1300-GS08, Manufacturer="OSRAM OPTO SEMICONDUCTORS", Manufacturer_Part_Number="LO Q976-PS-25", Package="LED 0603"
LD9: library part MCD-00051, "LED Bicolor", Alternate_Manufacturer=EVERLUCK, Alternate_Manufacturer_Part_Number=LE-RGW35280, Manufacturer="AVAGO TECHNOLOGIES", Manufacturer_Part_Number=HSMF-A201-A00J1
Q1 Q2: library part MCD-01969, "N-channel enhancement mode field-effect transistor", Manufacturer=Nexperia, Manufacturer_Part_Number=BSN20BK
R1: library part MCD-00394, "Resistor,150,0603,1%,1/10W", Manufacturer=YAGEO, Manufacturer_Part_Number=RC0603FR-07150RL, Package=R0603
R2: library part MCD-00338, "Resistor,120R,0603,1%,1/10W", Manufacturer=YAGEO, Manufacturer_Part_Number=RC0603FR-07120RL, Package=R0603
R3 R12 R15 R28 R30 R31 R52 R60 R79 R84 R85 R91 R94 R99 R100 R106 R109 R111 R129 R130 R133 R134 R142 R143 R144 R148 R151 R152 R166 R167 R173 R175 R183 R184 R185 R186 R187 R188 R191 R194 R199 R217 R231 R232 R298 R321 R355 R376 R395 R400 R402 R408 R414: library part MCD-00053, "Resistor,10K,0402,1%,1/16W", Manufacturer=YAGEO, Manufacturer_Part_Number=RC0402FR-0710KL, Package=R0402
R4 R5 R6 R17 R18 R19 R22 R25 R26 R27 R35 R45 R47 R50 R55 R67 R72 R81 R120 R123 R125 R126 R138 R141 R155 R156 R158 R168 R169 R170 R174 R201 R202 R206 R207 R209 R210 R213 R219 R220 R221 R223 R235 R238 R239 R246 R253 R266 R273 R274 R275 R277 R278 R282 R284 R285 R288 R294 R301 R304 R309 R314 R323 R330: library part MCD-00056, "Resistor,0R,0603,5%,1/10W", Manufacturer=YAGEO, Manufacturer_Part_Number=RC0603JR-070RL, Package=R0603
R7 R420: library part MCD-00223, "Resistor,100K,0603,1%,1/10W", Manufacturer=YAGEO, Manufacturer_Part_Number=RC0603FR-07100KL, Package=R0603
R8 R9: library part MCD-00184, "Resistor,3K3,0402,1%,1/16W", Manufacturer=YAGEO, Manufacturer_Part_Number=RC0402FR-073K3L, Package=R0402
R10 R11 R13 R14 R171 R189 R193 R224 R227 R228 R242 R247: library part MCD-00063, "Resistor,47K,0402,1%,1/16W", Manufacturer=YAGEO, Manufacturer_Part_Number=RC0402FR-0747KL, Package=R0402
R16 R20 R21 R23 R24 R29 R33 R34 R39 R48 R49 R51 R54 R56 R58 R61 R62 R63 R64 R65 R66 R68 R69 R70 R71 R73 R74 R75 R76 R77 R78 R80 R82 R87 R88 R89 R93 R95 R96 R97 R98 R101 R102 R103 R104 R105 R108 R110 R113 R114 R115 R116 R117 R118 R119 R121 R122 R124 R127 R128 R131 R132 R135 R136 R137 R139 R140 R161 R162 R177 R205 R208 R216 R229 R230 R233 R234 R236 R237 R240 R241 R244 R245 R250 R251 R255 R257 R258 R261 R262 R263 R271 R272 R280 R281 R283 R286 R287 R289 R292 R295 R296 R297 R300 R308 R316 R318 R319 R320 R322 R324 R325 R326 R331 R332 R333 R334 R335 R337 R338 R339 R340 R341 R342 R343 R344 R345 R347 R348 R349 R350 R351 R352 R353 R354 R356 R357 R358 R359 R360 R361 R362 R363 R364 R365 R366 R367 R368 R369 R370 R371 R372 R373 R374 R375 R378 R380 R381 R382 R384 R385 R386 R387 R389 R390 R391 R397 R398 R399 R401 R403 R404 R405 R406 R407 R409 R411 R413: library part MCD-00052, "Resistor,0R,0402,5%,1/16W", Manufacturer=YAGEO, Manufacturer_Part_Number=RC0402JR-070RL, Package=R0402
R32 R53 R57 R59 R218 R222 R252: library part MCD-00482, "Resistor,47R,0603,1%,1/10W", Manufacturer=YAGEO, Manufacturer_Part_Number=RC0603FR-0747RL, Package=R0603
R36 R225: library part MCD-00528, "Resistor,820R,0603,1%,1/10W", Manufacturer=YAGEO, Manufacturer_Part_Number=RC0603FR-07820RL, Package=R0603
R37: library part MCD-00570, "Resistor,8K06,0603,1%,1/10W", Manufacturer=YAGEO, Manufacturer_Part_Number=RC0603FR-078K06L, Package=R0603
R38 R145 R157 R164 R417 R418: library part MCD-00067, "Resistor,100R,0402,1%,1/16W", Manufacturer=YAGEO, Manufacturer_Part_Number=RC0402FR-07100RL, Package=R0402
R40 R150 R172 R416 R419: library part MCD-00059, "Resistor,100K,0402,1%,1/16W", Alternate_Manufacturer=YAGEO, Alternate_Manufacturer_Part_Number=RT0402FRE07100KL, Manufacturer_Part_Number=RC0402FR-07100KL, Package=R0402
R41 R146 R147 R154 R211 R212: library part MCD-00065, "Resistor,4K7,0402,1%,1/16W", Alternate_Manufacturer=YAGEO, Alternate_Manufacturer_Part_Number=RT0402FRE074K7L, Manufacturer_Part_Number=RC0402FR-074K7L, Package=R0402
R42 R179 R195: library part MCD-00461, "Resistor,360R,0402,1%,1/16W", Manufacturer=YAGEO, Manufacturer_Part_Number=RC0402FR-07360RL, Package=R0402
R43 R279 R377 R388 R392 R393 R394 R396: library part MCD-00061, "Resistor,1K,0402,1%,1/16W", Manufacturer=YAGEO, Manufacturer_Part_Number=RC0402FR-071KL, Package=R0402
R44 R182: library part MCD-00179, "Resistor,0R,0805,5%", Manufacturer=YAGEO, Manufacturer_Part_Number=RC0805JR-070RL, Package=R0805
R46 R178 R196: library part MCD-00441, "Resistor,270R,0402,1%,1/16W", Manufacturer=YAGEO, Manufacturer_Part_Number=RC0402FR-07270RL, Package=R0402
R83: library part MCD-00443, "Resistor,27K,0402,1%,1/16W", Manufacturer=YAGEO, Manufacturer_Part_Number=RC0402FR-0727KL, Package=R0402
R86 R92 R107 R336 R346: library part MCD-00164, "Resistor,220K,0402,1%,1/16W", Manufacturer=YAGEO, Manufacturer_Part_Number=RC0402FR-07220KL, Package=R0402
R90: library part MCD-00493, "Resistor,56K,0402,1%,1/16W", Manufacturer=YAGEO, Manufacturer_Part_Number=RC0402FR-0756KL, Package=R0402
R112: library part MCD-00499, "Resistor,620R,0402,1%,1/16W", Manufacturer=YAGEO, Manufacturer_Part_Number=RC0402FR-07620RL, Package=R0402
R149: library part MCD-00527, "Resistor,820R,0402,1%,1/16W", Manufacturer=YAGEO, Manufacturer_Part_Number=RC0402FR-07820RL, Package=R0402
R153: library part MCD-00055, "Resistor,2K7,0402,1%,1/16W", Manufacturer=YAGEO, Manufacturer_Part_Number=RC0402FR-072K7L, Package=R0402
R159: library part MCD-00593, "Ferrite bead, 600R @ 100MHz,  1.3A, 150mOhm, 0603", Manufacturer=MURATA, Manufacturer_Part_Number=BLM18KG601SN1D
R163: library part MCD-00064, "Resistor,510R,0402,1%,1/16W", Manufacturer=YAGEO, Manufacturer_Part_Number=RC0402FR-07510RL, Package=R0402
R165: library part MCD-00185, "Resistor,3K,0402,1%,1/16W", Manufacturer=YAGEO, Manufacturer_Part_Number=RC0402FR-073KL, Package=R0402
R176: library part MCD-00194, "Resistor,120R,0402,1%,1/16W", Manufacturer=YAGEO, Manufacturer_Part_Number=RC0402FR-07120RL, Package=R0402
R180 R328 R329: library part MCD-00178, "Resistor,470R,0402,1%,1/16W", Manufacturer=YAGEO, Manufacturer_Part_Number=RC0402FR-07470RL, Package=R0402
R181: library part MCD-00449, "Resistor,300R,0402,1%,1/16W", Manufacturer=YAGEO, Manufacturer_Part_Number=RC0402FR-07300RL, Package=R0402
R190 R192: library part MCD-00197, "Resistor,330R,0603,1%,1/10W", Manufacturer=YAGEO, Manufacturer_Part_Number=RC0603FR-07330RL, Package=R0603
R197 R198: library part MCD-00070, "Resistor,1K,0603,1%,1/10W", Manufacturer=YAGEO, Manufacturer_Part_Number=RC0603FR-071KL, Package=R0603
R200: library part MCD-00680, "Resistor, SMD PTS 100ohm @ 0°C Flat Chip Temperature Sensor", Manufacturer=VISHAY, Manufacturer_Part_Number=PTS060301B100RP100, Package=R0603
R203: library part MCD-00352, "Resistor,3K3,0603,1%,1/10W", Manufacturer=YAGEO, Manufacturer_Part_Number=RC0603FR-073K3L, Package=R0603
R204: library part MCD-00224, "Resistor,100R,0603,1%,1/10W", Manufacturer=YAGEO, Manufacturer_Part_Number=RC0603FR-07100RL, Package=R0603
R214 R215 R226 R243 R248 R249 R254 R256 R259 R260 R264 R265 R269 R270 R276 R290 R291 R293 R299 R302 R303 R305 R306 R310 R312 R313 R315 R317: library part MCD-01986, "Ferrite bead, 470ohms at 100MHz, 200mA, 0.6ohms DC max", Manufacturer=Murata, Manufacturer_Part_Number=BLM15BD471SN1D, Package=L0402
R267 R268: library part MCD-00047, "SMD Chip ferrite bead, 600R@100MHz +/-25%, 350mA, 500mohm DC, 0603, T=0.8mm", Manufacturer=TAI-TECH, Manufacturer_Part_Number=FCM1608KF-601T03
R410 R412: library part MCD-00564, "Resistor,49R9,0603,1%,1/10W", Manufacturer=YAGEO, Manufacturer_Part_Number=RC0603FR-0749R9L, Package=R0603
R415: library part MCD-00349, "Resistor,2K2,0603,1%,1/10W", Manufacturer=YAGEO, Manufacturer_Part_Number=RC0603FR-072K2L, Package=R0603
RV1: library part MCD-00575, "TRIMMER 10K OHM 0.5W PC PIN", Manufacturer=BOURNS, Manufacturer_Part_Number=3386P-1-103
SB1 SB2 SB3 SB4 SB5 SB6 SB7 SB8 SB9 SB10 SB11 SB12 SB13 SB14 SB15 SB16 SB17 SB18 SB19 SB20 SB21 SB22 SB23 SB24 SB25 SB26 SB27 SB28 SB29 SB30 SB31 SB32 SB33 SB34 SB35 SB36 SB37 SB38 SB39 SB40 SB43 SB44 SB45 SB46: library part MCD-00071, "Solder Bridge ON", Manufacturer=YAGEO, Manufacturer_Part_Number=RC0603JR-070RL, Package=SB0603
SB41 SB42 SB47 SB48 SB49 SB50 SB51 SB52: library part MCD-01618, "Solder Bridge 0402 ON", Manufacturer=YAGEO, Manufacturer_Part_Number=RC0402JR-070RL, Package=SB0402
SW1: library part MCD-00566, "Mechanical Slide Switches 1K2 BLK ACT GOLD STRT MNT", Manufacturer=EAO, Manufacturer_Part_Number=09.03290.01
T1 T2: library part MCD-00073, "NPN Bipolar Transistor", Alternate_Manufacturer="ON SEMICONDUCTOR", Alternate_Manufacturer_Part_Number="MMBT2222LT1G / MMBT2222ALT1G / MMBT2222ALT3G", Manufacturer_Part_Number=BSR14, Package=SOT23
TP1 TP10 TP12 TP17 TP18 TP19 TP20 TP21: library part MCD-00712, "RS Pro 1mm Red Test Terminal", Manufacturer=RS, Manufacturer_Part_Number=262-2185
TP2 TP3 TP4 TP5 TP6 TP7 TP8 TP9 TP11 TP13 TP14 TP15 TP16 TP22 TP23 TP26 TP27: library part MCD-00074, "Test Point 1mm", Manufacturer=n/a
TP24 TP25: library part MCD-01506, "Test Point trought hole 1mm/2mm", Manufacturer=n/a
TPG1 TPG2 TPG3 TPG4: library part MCD-00713, "Vero Technologies 1.02mm Black Terminal Post", Manufacturer=VERO, Manufacturer_Part_Number=20-2137
U1: library part MCD-00721, "LDO Voltage Regulator, Adjustable, 15V in, 1.1V drop, 1.25V to 15V/0.8A out, SOT-223-3", Manufacturer=STMICROELECTRONICS, Package=SOT223
U2: library part MCD-00668, "Low voltage 0.5 ohm single SPDT switch with break-before-make feature and 15 kV contact ESD protection", Manufacturer=STMICROELECTRONICS, Manufacturer_Part_Number=STG4160BJR, Package="Flip Chip 8"
U3 U4 U38 U40: library part MCD-00667, "4-line ESD protection for high speed lines", Manufacturer=STMICROELECTRONICS, Package=uQFN-10L
U5: library part MCD-01930, "STM32H7B3LIH6QU (crypto) 32H7B3LIH6QU$P2 Cut1.1 (Marking value = 32H7B3LIH6QU),TFBGA 225, 13x13 0.8 with footprint for socket IRONWOOD CS1222291MF", Manufacturer=STMICROELECTRONICS, Manufacturer_Part_Number="STM32H7B3LIH6QU 32H7B3LIH6QU$P2", Package="TFBGA225 13x13 0.8"
U6 U31 U32 U34 U35 U43 U44 U45: library part MCD-00170, "ESD protection 6V1", Manufacturer=STMICROELECTRONICS, Manufacturer_Part_Number=ESDALC6V1-1U2
U7: library part MCD-00569, "USB3320C,  Hi-Speed USB Host, Device or OTG PHY with ULPI Low Pin Interface", Manufacturer=MICROCHIP, Manufacturer_Part_Number=USB3320C-EZK-TR
U8 U23 U33: library part MCD-00251, "High power transient voltage suppressor, 7V breakdown", Manufacturer=STMICROELECTRONICS, Manufacturer_Part_Number=ESDA7P60-1U1M
U9: library part MCD-00152, "RS-232 transceiver with auto-power-down", Manufacturer=STMICROELECTRONICS
U10: library part MCD-00581, "LDO Linear Voltage Regulator IC Positive Adjustable 1 Output Adjustable 1.3A 6-DFN (3x3)", Manufacturer=STMICROELECTRONICS, Package="DFN6 (3x3)"
U11: library part MCD-00246, "Memory,Octo-SPI-NOR,512Mb,2048x16,133MHz,3V,DTR,BGA24, CMOS MXSMIO", Manufacturer=MACRONIX, Package=BGA24
U12: library part MCD-01345, "NOR FLASH 128Mbit 75ns - 64-ball LBGA (replacing PC28F128M29EWLA)", Manufacturer=MICRON, Manufacturer_Part_Number=MT28EW128ABA1LPC-0SIT, Package="64-ball LBGA 11 x 13mm"
U13: library part MCD-00078, "Ultra low drop-low noise BiCMOS voltage, regulators low ESR capacitors compatible", Manufacturer=STMICROELECTRONICS
U14 U15: library part MCD-01025, "LDO, 3.3V, 1.3A, Very low quiescent current BiCMOS voltage regulator", Manufacturer=STMICROELECTRONICS, Package=DFN6-3x3
U16: library part MCD-00562, "SDRAM 256MBit 166MHZ 90BGA", Alternate_Manufacturer=ISSI, Manufacturer_Part_Number=IS42S32800J-6BLI
U17: library part MCD-00560, "SRAM 16Mb 10ns 1Mx16 Async SRAM 3.3v", Manufacturer=ISSI
U18 U20: library part MCD-00247, "Quad Bidir ESD protection", Manufacturer=STMICROELECTRONICS
U19: library part MCD-00086, "Ultra low drop-low noise BiCMOS voltage, regulators low ESR capacitors compatible", Manufacturer=STMICROELECTRONICS
U21: library part MCD-00596, "STM32F723IEK  (STM32F7) BGA176", Manufacturer=STMICROELECTRONICS, Manufacturer_Part_Number=STM32F723IEK6
U22 U29 U39: library part MCD-00159, "500mA, Enhanced single channel power switches with active high enable pin", Alternate_Manufacturer="TEXAS INSTRUMENTS", Alternate_Manufacturer_Part_Number=TPS2051C, Manufacturer=STMICROELECTRONICS
U24: library part MCD-01482, "44 pins Interposer for WIFI module (MB1486 module is with INVENTEK ISM43362-M3G-L44)", Manufacturer=STMICROELECTRONICS, Manufacturer_Part_Number="MB1486 - WIFI MODULE WITH INVENTEK ISM43362-M3G-L44"
U25: library part MCD-00135, "Ultra-low-power 32-bit MCU ARM", Manufacturer=STMICROELECTRONICS
U26 U41: library part MCD-00649, "Common mode filter with ESD protection for USB 2.0 interface", Manufacturer=STMICROELECTRONICS
U27: library part MCD-01358, "Automotive dual-line Transil, transient voltage suppressor (TVS) for CAN bus 36V. Compliant with interfaces in automotive: CAN-FD, LIN, FlexRay, MOST, SENT, USB", Manufacturer=STMICROELECTRONICS, Manufacturer_Part_Number=ESDCAN05-2BWY, Package=SOT323-3L
U28: library part MCD-00129, "High-Speed CAN Flexible Data Rate Transceiver", Manufacturer=MICROCHIP, Manufacturer_Part_Number=MCP2562FDT-H/SN
U30: library part MCD-00163, "Very low capacitance ESD protection", Manufacturer=STMICROELECTRONICS
U36 U37: library part MCD-00681, "Smart sensor II dual-channel 1-bit, 4 MHz, second-order sigmadelta modulator with embedded PGLNA", Manufacturer=STMICROELECTRONICS, Package="QFN16 (4x4 mm)"
U42 U46 U47: library part MCD-00136, "Dual Transil array for ESD protection", Manufacturer=STMICROELECTRONICS
U48: library part MCD-00265, "Low-Power, Stereo Codec with Headphone Amp", Manufacturer="CIRRUS LOGIC"
U49: library part MCD-01066, "5 unidirectional Transil diodes ESD protection", Manufacturer=STMICROELECTRONICS, Package=SOT23-6L
X1: library part MCD-01036, "Crystal 24MHz, 6pF, +-20ppm, 80ohms max, SMD", Manufacturer=NDK, Manufacturer_Part_Number="NX2016SA 24MHz EXS00A-CS10820", Package="(2016) 2.0 x 1.6 x 0.45 mm"
X2: library part MCD-00091, "Crystal 32.768kHz, 6pF, +-20ppm, 50Kohms max, SMD", Manufacturer=NDK, Manufacturer_Part_Number="NX3215SA 32.768KHz EXS00A-MU00525"
X3: library part MCD-01014, "Oscillator 24Mhz, +-50ppm, Vcc:3.3V typ, square wave: [0.1Vcc;0.9Vcc], Enable pin", Alternate_Manufacturer=KC2520B24.0000C10E00, Alternate_Manufacturer_Part_Number="AVX Corp/Kyocera Corp", Manufacturer=NDK, Manufacturer_Part_Number="NZ2520SB 24MHz END4869A"
X4: library part MCD-00597, "Oscillator 25Mhz, +-50ppm, Vcc:3.3V typ, square wave: [0.1Vcc;0.9Vcc], Enable pin, SMD", Alternate_Manufacturer=NDK, Alternate_Manufacturer_Part_Number="NZ2520SB 25MHz END4869B", Manufacturer_Part_Number="NZ2520SH 25MHz END4869C"
Z1: library part MCD-00149, "Protection circuit Zener Diode", Manufacturer=LITTLEFUSE

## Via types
v1: diameter 0.6, hole 0.254, Top Layer to Bottom Layer, tented both sides, 1747 vias
v2: diameter 0.45, hole 0.2, Top Layer to Bottom Layer, tented both sides, 272 vias
v3: diameter 0.406, hole 0.203, Top Layer to Bottom Layer, tented both sides, 160 vias
v4: diameter 0.6, hole 0.25, Top Layer to Bottom Layer, tented both sides, 82 vias
v5: diameter 0.45, hole 0.25, Top Layer to Bottom Layer, tented both sides, 45 vias
v6: diameter 0.5, hole 0.25, Top Layer to Bottom Layer, tented both sides, 23 vias
v7: diameter 1.016, hole 0.508, Top Layer to Bottom Layer, tented both sides, 17 vias
v8: diameter 0.508, hole 0.254, Top Layer to Bottom Layer, tented both sides, 9 vias
v9: diameter 0.61, hole 0.305, Top Layer to Bottom Layer, tented both sides, 7 vias
v10: diameter 0.5, hole 0.254, Top Layer to Bottom Layer, tented both sides, 6 vias
v11: diameter 0.4, hole 0.2, Top Layer to Bottom Layer, tented both sides, 1 vias
v12: diameter 0.483, hole 0.254, Top Layer to Bottom Layer, tented both sides, 1 vias

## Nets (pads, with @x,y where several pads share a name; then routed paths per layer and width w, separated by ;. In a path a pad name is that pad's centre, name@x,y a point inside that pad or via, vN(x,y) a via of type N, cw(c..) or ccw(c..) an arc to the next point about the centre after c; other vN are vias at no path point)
1V8_AO: C21.2 R274.1 SB4.2 SB22.2 SB25.1 TP12.1 | length 303.3
  Top Layer w0.5: SB22.2@12.9,101 v1(12.9,102.4) ; v1(15.748,128.016) 18.161,128.016 20.828,130.683 20.828,133.858 24.003,137.033 v1(24.003,138.43) ; v1(87.884,155.194) 87.887,155.194 88.584,154.497 C21.2@88.584,152.146 ; v1(123.317,67.818) SB25.1@124.468,67.818
  Signal Layer 2 w0.5: v1(21.082,151.638) 21.082,153.924 23.258,156.1 56.498,156.1 57.404,155.194 v1(87.884,155.194) ; v1(60.579,47.244) 62.992,44.831 111.252,44.831 124.968,58.547 124.968,66.167 v1(123.317,67.818)
  Bottom Layer w0.5: R274.1@13.27,135.128 R274.1@13.27,134.874 13.27,134.112 13.778,133.604 13.778,128.462 ; TP12.1@15.494,101.346 14.854,101.346 13.8,102.4 v1(12.9,102.4) v1(12.9,103.3) 12.9,127.54 13.8,128.44 14.224,128.016 v1(15.748,128.016) ; TP12.1@15.5,101.3 19.2,101.3 20,102.1 21.4,102.1 22,101.5 22,99.514 22.6,98.914 23.641,98.914 31.496,91.059 31.496,76.327 v1(60.579,47.244) ; v1(21.082,151.638) 21.082,148.59 24.003,145.669 v1(24.003,138.43)
1V8_CODEC: C56.2 C58.2 C59.2 C60.1 C61.1 SB25.2 SB26.2 U48.5 U48.12 U48.27 | length 10.5
  Top Layer w0.254: C56.2@132.888,70.751 v1@132.888,71.674
  Top Layer w0.381: C59.2@135.578,67.818 135.578,68.268 v1(135.763,68.453)
  Top Layer w0.508: SB26.2@125.568,66.294 SB25.2@125.568,67.818 126.938,67.818 C60.1@127,67.756 C61.1@128.27,67.756 129.097,67.756 v1(129.286,67.945) 129.355,67.876 C58.2@130.048,67.876
  Bottom Layer w0.254: v1(129.286,67.945) 129.298,67.945 129.667,67.576 U48.27@130.163,67.576 ; U48.5@132.838,70.751 132.838,71.497 v1@132.969,71.628 ; U48.12@135.013,68.576 135.64,68.576 v1(135.763,68.453)
  other v1: 132.969,71.755
1V8_LDO: C47.2 SB22.1 U13.5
